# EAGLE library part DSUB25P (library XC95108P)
IBM PC/AT Parallel Connector
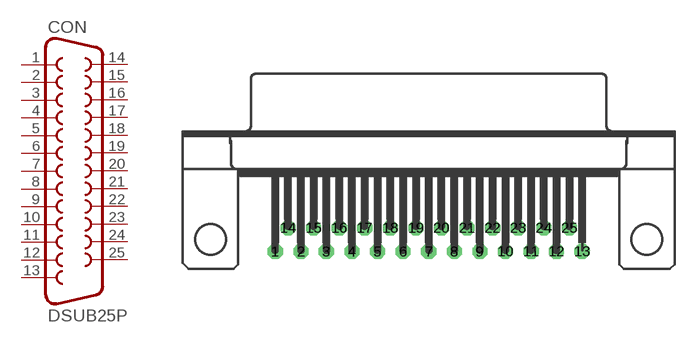
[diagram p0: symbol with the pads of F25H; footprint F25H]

Designator prefix CON

## DSUB25P  [F25H]
1  1  pas
2  2  pas
3  3  pas
4  4  pas
5  5  pas
6  6  pas
7  7  pas
8  8  pas
9  9  pas
10  10  pas
11  11  pas
12  12  pas
13  13  pas
14  14  pas
15  15  pas
16  16  pas
17  17  pas
18  18  pas
19  19  pas
20  20  pas
21  21  pas
22  22  pas
23  23  pas
24  24  pas
25  25  pas

## Footprint F25H (pad centres in mm)
DSUB25P Female
drill 1.092 octagon: 1 -16.561,-10.16; 2 -13.792,-10.16; 3 -11.049,-10.16; 4 -8.28,-10.16; 5 -5.512,-10.16; 6 -2.769,-10.16; 7 0,-10.16; 8 2.769,-10.16; 9 5.512,-10.16; 10 8.28,-10.16; 11 11.049,-10.16; 12 13.792,-10.16; 13 16.561,-10.16; 14 -15.189,-7.62; 15 -12.421,-7.62; 16 -9.652,-7.62; 17 -6.909,-7.62; 18 -4.14,-7.62; 19 -1.372,-7.62; 20 1.372,-7.62; 21 4.14,-7.62; 22 6.909,-7.62; 23 9.652,-7.62; 24 12.421,-7.62; 25 15.189,-7.62
hole 3.302 at -23.495,-8.89
hole 3.302 at 23.495,-8.89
